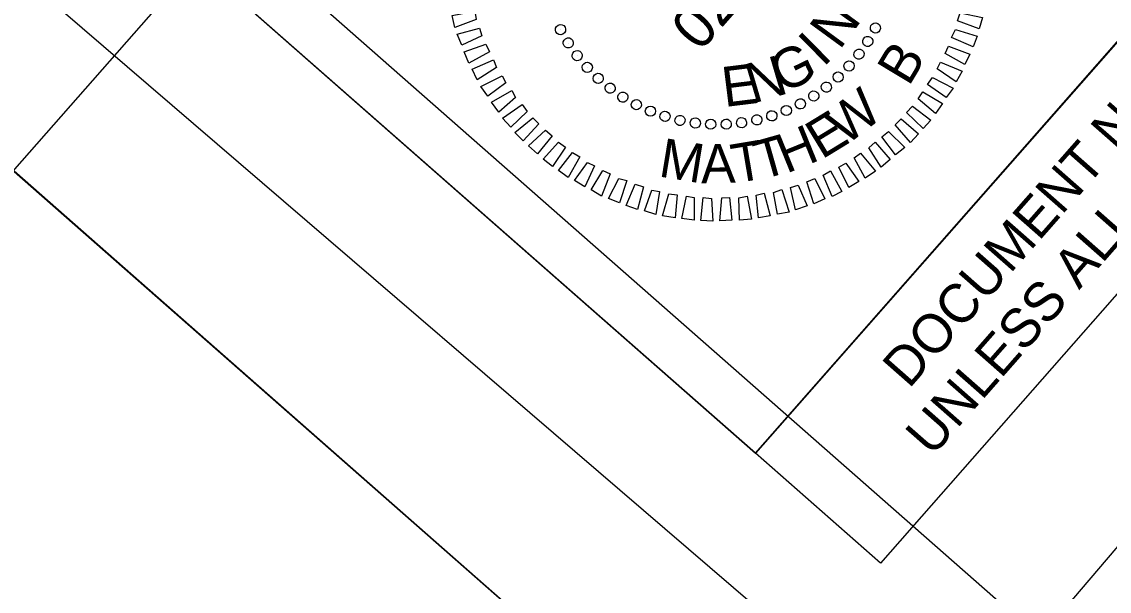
# Model space of a CAD drawing. Extents: x 2189835 to 2191772, y 387461 to 389531.
# Drawn here: x 2190828.7 to 2190982.4, y 389152 to 389232.4 of the extents above; entities that cross this region are included whole.
import ezdxf

# ---------------------------------------------------------------- set-up
doc = ezdxf.new("R2010")
doc.units = 0
for name, color, linetype in [('Sheet Clip Boundary CELL', 7, 'Continuous'), ('Sheet Layout Plan Border', 7, 'Continuous'), ('Sheet Plan CELL', 7, 'Continuous'), ('Sheet Plan Layout CELL', 7, 'Continuous'), ('Sheet Professional Seal CELL', 7, 'Continuous'), ('Sheet Sticker Exception Certification CELL', 7, 'Continuous')]:
    doc.layers.add(name, color=color, linetype=linetype)

msp = doc.modelspace()

# ---------------------------------------------------------------- linework, layer by layer
at = {"layer": 'Sheet Clip Boundary CELL'}
msp.add_lwpolyline([(2190233.88, 388250.3), (2190718.45, 387881.26), (2190850.4, 387777.99), (2191678.63, 388725.5), (2191058.62, 389246.4), (2190957.74, 389128.02), (2190818.15, 389247.91), (2190051.03, 388378.47)], close=True, dxfattribs=at)
at = {"layer": 'Sheet Layout Plan Border'}
msp.add_lwpolyline([(2190847.19, 387643.49), (2191771.58, 388694.94), (2191141.84, 389248.59), (2191016.87, 389106.45), (2190858.04, 389246.09), (2190058.62, 388336.78)], close=True, dxfattribs=at)
at = {"layer": 'Sheet Plan CELL'}
for points in [[(2190749.93, 387600.92), (2189961.36, 388294.17), (2190819.67, 389270.52), (2190932.38, 389171.45), (2191064.47, 389321.68), (2191740.35, 388727.47)], [(2190847.89, 389245.71), (2190913.95, 389320.85), (2190998.45, 389246.57), (2190932.38, 389171.45)]]:
    msp.add_lwpolyline(points, close=True, dxfattribs=at)
at = {"layer": 'Sheet Plan Layout CELL'}
for points in [[(2190952.63, 389101.43), (2191110.61, 389281.13), (2190951.8, 389420.79), (2190793.79, 389241.07)], [(2189961.36, 388294.17), (2190749.93, 387600.92), (2191740.34, 388727.46), (2191110.6, 389281.11), (2190952.63, 389101.43), (2190793.79, 389241.07)]]:
    msp.add_lwpolyline(points, close=True, dxfattribs=at)
at = {"layer": 'Sheet Professional Seal CELL'}
for p, q in [((2190904.81, 389231.27), (2190904.81, 389231.27)), ((2190949.37, 389231.54), (2190949.37, 389231.54)), ((2190905.93, 389229.36), (2190905.93, 389229.36)), ((2190948.22, 389229.62), (2190948.22, 389229.62)), ((2190907.22, 389227.64), (2190907.22, 389227.64)), ((2190947.03, 389227.8), (2190947.03, 389227.8)), ((2190908.6, 389225.96), (2190908.6, 389225.96)), ((2190945.62, 389226.12), (2190945.62, 389226.12)), ((2190910.16, 389224.4), (2190910.16, 389224.4)), ((2190944.06, 389224.56), (2190944.06, 389224.56)), ((2190911.85, 389222.99), (2190911.85, 389222.99)), ((2190942.38, 389223.17), (2190942.38, 389223.17)), ((2190913.66, 389221.8), (2190913.66, 389221.8)), ((2190940.66, 389221.89), (2190940.66, 389221.89)), ((2190915.58, 389220.65), (2190915.58, 389220.65)), ((2190917.56, 389219.72), (2190917.56, 389219.72)), ((2190936.75, 389219.86), (2190936.75, 389219.86)), ((2190938.75, 389220.77), (2190938.75, 389220.77)), ((2190919.59, 389219), (2190919.59, 389219)), ((2190921.71, 389218.47), (2190921.71, 389218.47)), ((2190923.9, 389218.08), (2190923.9, 389218.08)), ((2190926.04, 389217.87), (2190926.04, 389217.87)), ((2190928.27, 389217.91), (2190928.27, 389217.91)), ((2190930.42, 389218.09), (2190930.42, 389218.09)), ((2190932.59, 389218.52), (2190932.59, 389218.52)), ((2190934.72, 389219.05), (2190934.72, 389219.05))]:
    msp.add_line(p, q, dxfattribs=at)
for points in [[(2190892.92, 389232.71), (2190889.94, 389231.59), (2190889.55, 389233.27), (2190892.77, 389233.91)], [(2190961.31, 389233.64), (2190964.47, 389233), (2190963.98, 389231.38), (2190960.93, 389232.52)], [(2190893.75, 389230.39), (2190890.93, 389229.07), (2190890.26, 389230.66), (2190893.43, 389231.47)], [(2190960.65, 389231.3), (2190963.69, 389230.36), (2190963.16, 389228.84), (2190960.06, 389230.16)], [(2190894.82, 389228.13), (2190891.91, 389226.55), (2190891.24, 389228.14), (2190894.32, 389229.23)], [(2190959.64, 389228.93), (2190962.66, 389227.81), (2190961.97, 389226.35), (2190959.21, 389227.9)], [(2190895.81, 389225.92), (2190893.09, 389224.18), (2190892.36, 389225.69), (2190895.39, 389227.03)], [(2190958.55, 389226.69), (2190961.61, 389225.41), (2190960.76, 389223.9), (2190958.05, 389225.74)], [(2190897.13, 389223.78), (2190894.59, 389221.88), (2190893.58, 389223.23), (2190896.6, 389224.77)], [(2190957.38, 389224.52), (2190960.32, 389223.02), (2190959.34, 389221.68), (2190956.71, 389223.52)], [(2190898.5, 389221.71), (2190896.16, 389219.64), (2190895.11, 389221.02), (2190897.98, 389222.7)], [(2190956.03, 389222.52), (2190958.8, 389220.83), (2190957.83, 389219.42), (2190955.35, 389221.52)], [(2190900.16, 389219.73), (2190897.83, 389217.52), (2190896.68, 389218.79), (2190899.42, 389220.71)], [(2190954.57, 389220.47), (2190957.18, 389218.52), (2190956.06, 389217.31), (2190953.74, 389219.6)], [(2190901.8, 389217.96), (2190899.58, 389215.58), (2190898.41, 389216.74), (2190900.96, 389218.83)], [(2190952.95, 389218.7), (2190955.4, 389216.56), (2190954.27, 389215.35), (2190952.12, 389217.83)], [(2190903.65, 389216.28), (2190901.62, 389213.73), (2190900.34, 389214.85), (2190902.74, 389217.07)], [(2190951.19, 389216.92), (2190953.51, 389214.63), (2190952.19, 389213.58), (2190950.25, 389216.15)], [(2190905.56, 389214.67), (2190903.72, 389211.96), (2190902.38, 389213), (2190904.59, 389215.38)], [(2190949.31, 389215.38), (2190951.42, 389212.93), (2190950.15, 389211.85), (2190948.41, 389214.57)], [(2190907.57, 389213.31), (2190905.95, 389210.41), (2190904.57, 389211.41), (2190906.53, 389213.95)], [(2190947.22, 389213.82), (2190949.33, 389211.3), (2190947.91, 389210.29), (2190946.34, 389213.19)], [(2190909.67, 389212.07), (2190908.31, 389209.07), (2190906.83, 389209.97), (2190908.68, 389212.54)], [(2190945.15, 389212.44), (2190946.99, 389209.84), (2190945.59, 389209), (2190944.19, 389211.88)], [(2190911.87, 389210.94), (2190910.63, 389207.77), (2190909.19, 389208.64), (2190910.85, 389211.37)], [(2190914.2, 389209.96), (2190913.17, 389206.81), (2190911.64, 389207.42), (2190913.08, 389210.28)], [(2190940.79, 389210.28), (2190942.19, 389207.39), (2190940.64, 389206.69), (2190939.65, 389209.81)], [(2190942.99, 389211.34), (2190944.6, 389208.4), (2190943.23, 389207.74), (2190941.97, 389210.71)], [(2190916.56, 389209.09), (2190915.75, 389205.88), (2190914.12, 389206.45), (2190915.41, 389209.44)], [(2190936.11, 389208.72), (2190937.14, 389205.5), (2190935.49, 389205.21), (2190934.93, 389208.29)], [(2190938.41, 389209.3), (2190939.67, 389206.41), (2190938.04, 389205.84), (2190937.33, 389208.98)], [(2190918.84, 389208.43), (2190918.31, 389205.17), (2190916.72, 389205.7), (2190917.73, 389208.6)], [(2190921.35, 389207.96), (2190921.03, 389204.71), (2190919.28, 389204.98), (2190920.14, 389208.09)], [(2190923.75, 389207.58), (2190923.72, 389204.36), (2190922, 389204.6), (2190922.64, 389207.76)], [(2190926.2, 389207.43), (2190926.38, 389204.22), (2190924.67, 389204.31), (2190924.99, 389207.56)], [(2190928.71, 389207.56), (2190929.06, 389204.39), (2190927.37, 389204.28), (2190927.62, 389207.52)], [(2190931.21, 389207.76), (2190931.82, 389204.51), (2190930.13, 389204.39), (2190930.02, 389207.54)], [(2190933.63, 389208.17), (2190934.48, 389204.97), (2190932.8, 389204.71), (2190932.48, 389207.92)]]:
    msp.add_lwpolyline(points, close=True, dxfattribs=at)
for centre, major_axis in [((2190904.85, 389231.29), (-0.637, -0.336)), ((2190949.34, 389231.52), (0.64, -0.329)), ((2190905.95, 389229.4), (-0.605, -0.39)), ((2190948.25, 389229.62), (0.609, -0.384)), ((2190947.01, 389227.82), (0.574, -0.435)), ((2190907.21, 389227.61), (-0.569, -0.441)), ((2190908.63, 389225.95), (-0.528, -0.489)), ((2190945.61, 389226.14), (0.533, -0.484)), ((2190910.18, 389224.41), (-0.484, -0.533)), ((2190944.07, 389224.59), (0.489, -0.528)), ((2190911.87, 389223.01), (-0.435, -0.574)), ((2190913.67, 389221.76), (-0.384, -0.609)), ((2190940.62, 389221.91), (0.39, -0.605)), ((2190942.4, 389223.17), (0.441, -0.569)), ((2190915.57, 389220.68), (-0.329, -0.64)), ((2190938.73, 389220.8), (0.336, -0.637)), ((2190917.55, 389219.77), (-0.272, -0.667)), ((2190919.61, 389219.03), (-0.213, -0.688)), ((2190934.7, 389219.11), (0.22, -0.686)), ((2190936.75, 389219.87), (0.279, -0.664)), ((2190921.73, 389218.47), (-0.152, -0.704)), ((2190923.89, 389218.1), (-0.09, -0.714)), ((2190926.07, 389217.93), (-0.028, -0.719)), ((2190928.26, 389217.94), (0.035, -0.719)), ((2190930.43, 389218.14), (0.098, -0.713)), ((2190932.59, 389218.53), (0.16, -0.702))]:
    msp.add_ellipse(centre, major_axis=major_axis, ratio=0.999708, dxfattribs=at)
at = {"layer": 'Sheet Sticker Exception Certification CELL'}
for p, q in [((2190932.38, 389171.45), (2191064.46, 389321.69)), ((2191082.11, 389306.17), (2190950.03, 389155.94)), ((2190950.03, 389155.94), (2190932.38, 389171.45))]:
    msp.add_line(p, q, dxfattribs=at)

# ---------------------------------------------------------------- texts
at = {"layer": 'Sheet Professional Seal CELL'}
for s, height, rotation, p in [('027771', 5.998, 48.8014, (2190924.56, 389228.01)), ('N', 5.64, 53.8578, (2190944.27, 389228.29)), ('I', 5.64, 44.5026, (2190941.95, 389225.87)), ('G', 5.64, 25.7916, (2190936.21, 389222.2)), ('B', 5.5, 59.0219, (2190954.04, 389223.15)), ('N', 5.64, 16.4353, (2190932.01, 389220.82)), ('E', 5.64, 7.0783, (2190928, 389220.34)), ('W', 5.5, 37.9707, (2190945.11, 389214.77)), ('E', 5.5, 31.3877, (2190941.75, 389212.89)), ('T', 5.5, 15.8461, (2190933.15, 389210.04)), ('H', 5.5, 22.1429, (2190936.73, 389210.91)), ('M', 5.5, 350.6877, (2190918.56, 389210.57)), ('A', 5.5, 1.3635, (2190924.72, 389209.56)), ('T', 5.5, 9.5493, (2190929.5, 389209.57))]:
    msp.add_text(s, height=height, rotation=rotation, dxfattribs=at).set_placement(p)
at = {"layer": 'Sheet Sticker Exception Certification CELL'}
for s, p in [('DOCUMENT NOT CONSIDERED FINAL', (2190954.07, 389180.45)), ('UNLESS ALL SIGNATURES COMPLETED', (2190957.33, 389170.83))]:
    msp.add_text(s, height=5.5, rotation=48.6794, dxfattribs=at).set_placement(p)

doc.saveas('drawing.dxf')
